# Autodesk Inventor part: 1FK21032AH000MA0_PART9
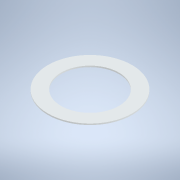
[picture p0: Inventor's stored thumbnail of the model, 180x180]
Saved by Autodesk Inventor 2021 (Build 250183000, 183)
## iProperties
Created: 2025-04
Part Number: 1FK21032AH000MA0_PART9
Material: Generic
Catalog Web Link: www.3dfindit.com
Description: -Servo synchronous motor
Document SubType Name: Modeling
Designer: psAdmin
Mass: 0.211555 g
Surface Area: 9.31012 cm^2
Volume: 0.211555 cm^3
Density: 1 g/cm^3
Appearance: PSOLRGB-212-217-219
Category: PARTsolutions
Title: 1FK21032AH000MA0_PART9
Author: Cadenas PARTsolutions
Comments: Servo synchronous motor
Sending System: PARTsolutions
Preprocessor: ST-DEVELOPER v19.3
PSOL_IDENT_0: {$CADENAS_DATA/23d-libs/siemens_ag/_cat_/45/10/1fk21032ah000ma0.prj},213 {VTYP=3D},{NB=1FK21032AH000
PSOL_IDENT_1: MA0_PART9},{LINA=1FK21032AH000MA0_PART9},{NN=1FK21032AH000MA0_PART9},{NOPRJ=TRUE},{DATE=19.08.2025 1
PSOL_IDENT_2: 4:00:35},{GEOMDATE=30.07.2025 02:02:03},{VERSION=},{LINEID=10},{WBVAR=},{WBNUMERIC=}  {NB=1FK21032AH
PSOL_IDENT_3: 000MA0_PART9},{LINA=1FK21032AH000MA0_PART9},{KT=DUMMY},{PREVIEW=../../../_pool_/14/8e/p_d211_xx_0042
PSOL_IDENT_4: 6j.png},{DESCSHORT=SIMOTICS S-1FK2 HD, SINAMICS S210 3AC 400V-480V, 0.59 Nm, 4500 rpm},{DESCLONG=SIM
PSOL_IDENT_5: OTICS S-1FK2 HD servo motor M0=0.64 Nm; PN = 0.28 kW at nN=4500 rpm (380-480 V); PN = 0.167 kW at nN=
PSOL_IDENT_6: 2500 rpm (200-240 V); degree of protection IP64; cylindrical shaft D14 x 30 mm; absolute encoder 22-
PSOL_IDENT_7: bit + 12-bit multiturn (encoder AM22DQC); with OCC interface; plug size M17, rotatable; SIMOTICS S-1
PSOL_IDENT_8: FK2 servomotorfor a wide range of uses in industrial environments. SIMOTICS S‑1FK2 servomotors are c
PSOL_IDENT_9: ompact synchronous motors with a high dynamic performance that set themselves apart as a result of t
PSOL_IDENT_10: heir high power density, degree of protection and overload capability. The motors are available in t
PSOL_IDENT_11: wo variants: as High Dynamic variant (highest dynamic performance as a result of the low intrinsic m
PSOL_IDENT_12: oment of inertia for applications demanding a high dynamic performance with low moved masses) - and
PSOL_IDENT_13: as Compact variant (precise and stable closed-loop control for medium up to large moved masses as a
PSOL_IDENT_14: result of a medium intrinsic moment of inertia). SIMOTICSS‑1FK2 servomotors fully exploit their stre
PSOL_IDENT_15: ngths in a system with the SINAMICSS210 frequency converter and simple connection using the one cabl
PSOL_IDENT_16: e connection (OCC). Advantages include the short control and positioning times, fast and precise cor
PSOL_IDENT_17: rection of disturbing quantities as well as stable control with a high dynamic performance. The serv
PSOL_IDENT_18: o motors can be configured to address a wide range of requirements. For example with and without hol
PSOL_IDENT_19: ding brake, IP64 or IP65 degree of protection, singleturn or multiturn absolute encoders - to name j
PSOL_IDENT_20: ust a few. Further, the servomotors are available in different shaft heights extending from 20 to 10
PSOL_IDENT_21: 0. A shaft sealing ring is available to achieve an IP65 degree of protection and for subsequent moun
PSOL_IDENT_22: ting at the motor or as spare part. SIMOTICS - the optimum motor for each and every motion control a
PSOL_IDENT_23: pplication.},{INTNO=195125335004},{SUPPLIERALTNO=1FK2103-2AH00-0MA0},{MANUID=1FK21032AH000MA0},{MANU
PSOL_IDENT_24: NAME=Siemens},{MANUTYPEDESC=SYNCHRONOUS MOTOR 1FK2 HD 0,64 NM},{AAU732=SIMOTICS},{AAO057=S-1FK2},{AA
PSOL_IDENT_25: U734=SIMOTICS S-1FK2 HD servo motor M0=0.64 Nm; PN = 0.28 kW at nN=4500 rpm (380-480 V); PN = 0.167
PSOL_IDENT_26: kW at nN=2500 rpm (200-240 V); degree of protection IP64; cylindrical shaft D14 x 30 mm; absolute en
PSOL_IDENT_27: coder 22-bit + 12-bit multiturn (encoder AM22DQC); with OCC interface; plug size M17, rotatable;},{A
PSOL_IDENT_28: AW338=SYNCHRONOUS MOTOR 1FK2 HD 0,64 NM},{AAO742=SIMOTICS},{AAO663=4034106444624},{NOCUPEROU=1},{PRI
PSOL_IDENT_29: CEQUANTITY=1},{QUANTITYMIN=1},{QUANTITYINT=1},{CTN=85015100},{COO=RO},{AAO676=1FK2103-2AH00-0MA0},{A
PSOL_IDENT_30: AO677=Siemens AG},{ORDERUNIT=C62},{CONTENTUNIT=C62}
NB: 1FK21032AH000MA0_PART9
NT: Servo synchronous motor
NBSYN: $MANUID._PART9
LINA: 1FK21032AH000MA0_PART9
CATALOG: SIEMENS
PREVIEW: ../../../_pool_/14/8e/p_d211_xx_00426j.png
DESCSHORT: SIMOTICS S-1FK2 HD, SINAMICS S210 3AC 400V-480V, 0.59 Nm, 4500 rpm
DESCLONG: SIMOTICS S-1FK2 HD servo motor M0=0.64 Nm; PN = 0.28 kW at nN=4500 rpm (380-480 V); PN = 0.167 kW at nN=2500 rpm (200-240 V); degree of protection IP64; cylindr
INTNO: 195125335004
SUPPLIERALTNO: 1FK2103-2AH00-0MA0
MANUID: 1FK21032AH000MA0
MANUNAME: Siemens
MANUTYPEDESC: SYNCHRONOUS MOTOR 1FK2 HD 0,64 NM
AAU732: SIMOTICS
AAO057: S-1FK2
AAU734: SIMOTICS S-1FK2 HD servo motor M0=0.64 Nm; PN = 0.28 kW at nN=4500 rpm (380-480 V); PN = 0.167 kW at nN=2500 rpm (200-240 V); degree of protection IP64; cylindr
AAW338: SYNCHRONOUS MOTOR 1FK2 HD 0,64 NM
AAO742: SIMOTICS
AAO663: 4034106444624.0
NOCUPEROU: 1
PRICEQUANTITY: 1
QUANTITYMIN: 1
QUANTITYINT: 1
CTN: 85015100
COO: RO
ARTICLENO: 1FK21032AH000MA0_PART9
BOMINFO: 1FK21032AH000MA0_PART9
CREATOR: CADENAS GmbH
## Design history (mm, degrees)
feature "2025_04_17_15_00_20_0760"
body "Solid1"
